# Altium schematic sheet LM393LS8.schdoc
size 127 x 101 mm
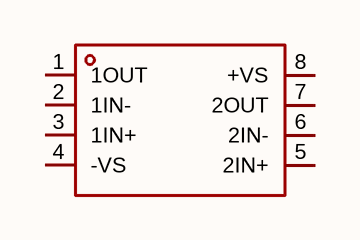
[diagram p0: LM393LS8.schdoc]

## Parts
U?  lm393ls8  [SOP-8_L4.9-W3.9-P1.27-LS6.0-BL]  (value not drawn)

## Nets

Not connected (* = marked no-connect by the designer): U? 1(1OUT) 2(1IN-) 3(1IN+) 4(-VS) 5(2IN+) 6(2IN-) 7(2OUT) 8(+VS)

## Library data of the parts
U? = lm393ls8: 比较器数:双路;输入失调电压(Vos):4mV;输入偏置电流(Ib):65nA;; Manufacturer: TECH PUBLIC(台舟); AddInBom: yes; ModelId: 75c24a7891ee4dd6bdac16a7163ff87e; ModelName: SOP-8_L4.9-W3.9-P1.27-LS6.0-BL-1; ModelTransform: 192.913,236.22,0,0,0,0,-0.393,2.749,0; Number of Channels: 双路; Vos - Input Offset Voltage: 4mV; Ib - Input Bias Current: 65nA; Propagation Delay Time: 350ns; Output Mode: MOS；CMOS；ECL；DTL；TTL; Quiescent Current: 600uA; Maximum Power Supply Range (Vdd-Vss): 30V; Single Supply: 3V~30V; Dual Supply: -15V~-1.5V；1.5V~15V; Input Offset Current(Ios): 5nA; Response Time (tr): 1.4us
